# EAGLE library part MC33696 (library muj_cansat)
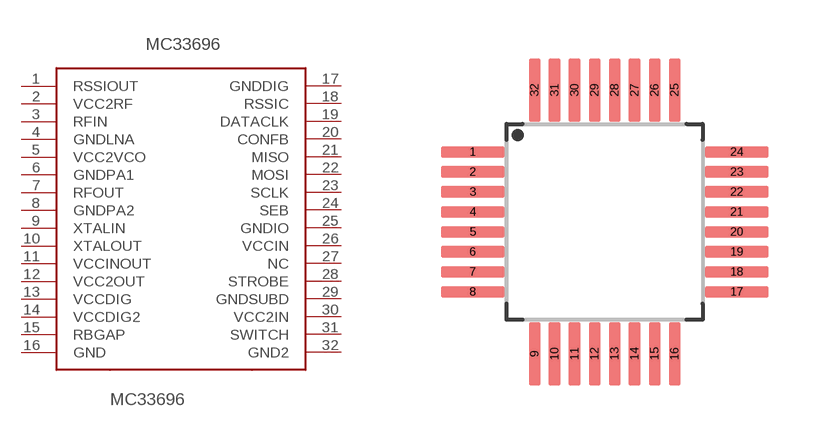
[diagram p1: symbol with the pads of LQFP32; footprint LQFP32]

Designator prefix -

## MC33696  [LQFP32]
1  RSSIOUT
2  VCC2RF
3  RFIN
4  GNDLNA
5  VCC2VCO
6  GNDPA1
7  RFOUT
8  GNDPA2
9  XTALIN
10  XTALOUT
11  VCCINOUT
12  VCC2OUT
13  VCCDIG
14  VCCDIG2
15  RBGAP
16  GND
17  GNDDIG
18  RSSIC
19  DATACLK
20  CONFB
21  MISO
22  MOSI
23  SCLK
24  SEB
25  GNDIO
26  VCCIN
27  NC
28  STROBE
29  GNDSUBD
30  VCC2IN
31  SWITCH
32  GND2

## Footprint LQFP32 (pad centres in mm)
LQFP 32
smd 1.6 x 0.3: 1 -3.3,1.75; 2 -3.3,1.25; 3 -3.3,0.75; 4 -3.3,0.25; 5 -3.3,-0.25; 6 -3.3,-0.75; 7 -3.3,-1.25; 8 -3.3,-1.75; 17 3.3,-1.75; 18 3.3,-1.25; 19 3.3,-0.75; 20 3.3,-0.25; 21 3.3,0.25; 22 3.3,0.75; 23 3.3,1.25; 24 3.3,1.75
smd 0.3 x 1.6: 9 -1.75,-3.3; 10 -1.25,-3.3; 11 -0.75,-3.3; 12 -0.25,-3.3; 13 0.25,-3.3; 14 0.75,-3.3; 15 1.25,-3.3; 16 1.75,-3.3; 25 1.75,3.3; 26 1.25,3.3; 27 0.75,3.3; 28 0.25,3.3; 29 -0.25,3.3; 30 -0.75,3.3; 31 -1.25,3.3; 32 -1.75,3.3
